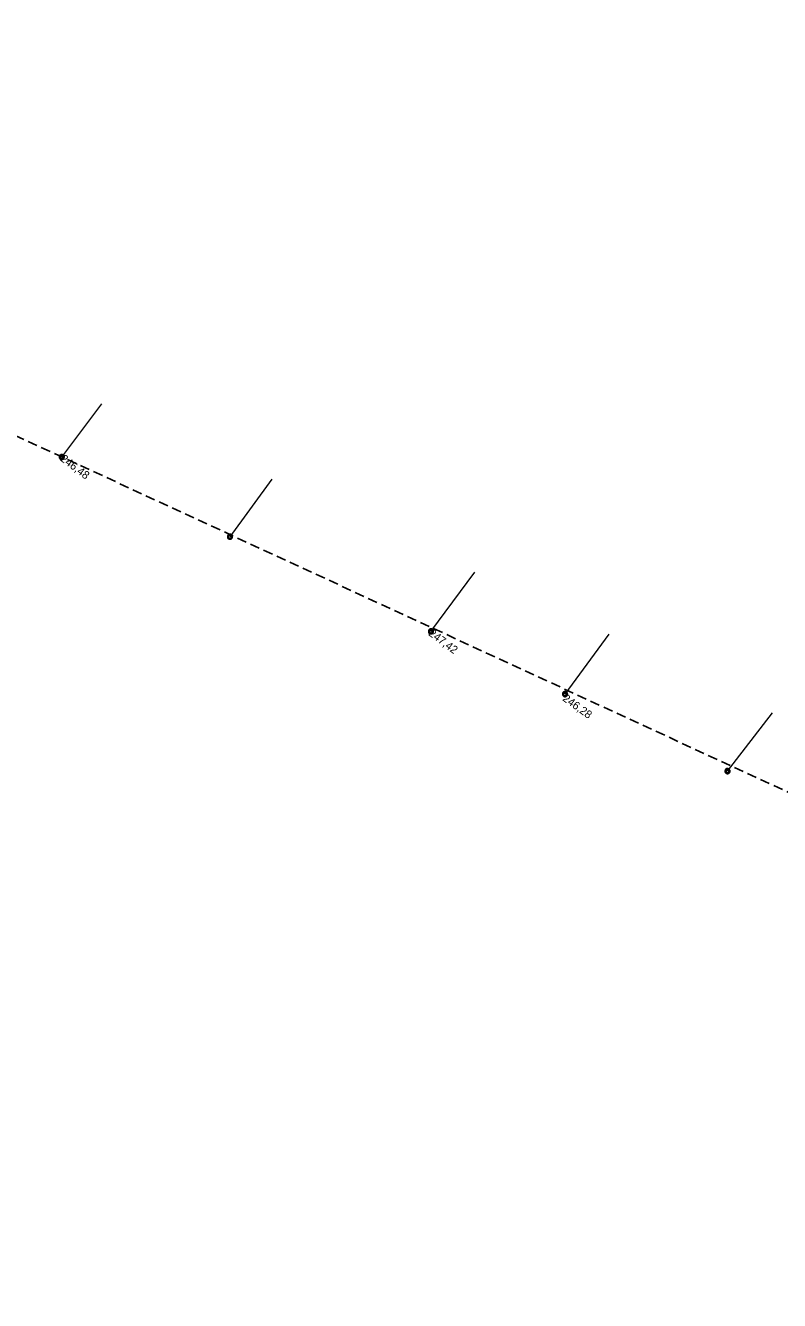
# Model space of a CAD drawing. Extents: x -735085 to -733500, y -1044153 to -1043402.
# Drawn here: x -734591.8 to -734516.4, y -1043690.4 to -1043562.9 of the extents above; entities that cross this region are included whole.
import ezdxf

# ---------------------------------------------------------------- set-up
doc = ezdxf.new("R2010")
doc.units = 0
doc.header["$LTSCALE"] = 0.32
doc.linetypes.add('MEDIUM_DASHED', pattern=[4.5, 3, -1.5])
doc.layers.add('16', color=7, linetype='Continuous')
for name, color, linetype, lineweight in [('18', 7, 'Continuous', 13), ('49', 7, 'Continuous', 13), ('63', 7, 'MEDIUM_DASHED', 25)]:
    doc.layers.add(name, color=color, linetype=linetype, lineweight=lineweight)

msp = doc.modelspace()

# ---------------------------------------------------------------- linework, layer by layer
at = {"layer": '18'}
for points in [[(-734587.874, -1043606.063), (-734587.88, -1043606.007), (-734587.897, -1043605.954), (-734587.926, -1043605.905), (-734587.964, -1043605.864), (-734588.01, -1043605.832), (-734588.062, -1043605.81), (-734588.117, -1043605.799), (-734588.173, -1043605.801), (-734588.228, -1043605.814), (-734588.279, -1043605.839), (-734588.323, -1043605.874), (-734588.359, -1043605.917), (-734588.384, -1043605.967), (-734588.399, -1043606.022), (-734588.402, -1043606.078), (-734588.393, -1043606.133), (-734588.372, -1043606.186), (-734588.341, -1043606.232), (-734588.301, -1043606.271), (-734588.253, -1043606.301), (-734588.2, -1043606.32), (-734588.144, -1043606.327), (-734588.088, -1043606.323), (-734588.034, -1043606.306), (-734587.985, -1043606.279), (-734587.943, -1043606.241), (-734587.91, -1043606.196), (-734587.887, -1043606.145), (-734587.875, -1043606.09)], [(-734587.933, -1043606.066), (-734587.939, -1043606.017), (-734587.957, -1043605.971), (-734587.985, -1043605.93), (-734588.022, -1043605.897), (-734588.066, -1043605.875), (-734588.114, -1043605.863), (-734588.163, -1043605.863), (-734588.211, -1043605.875), (-734588.255, -1043605.898), (-734588.292, -1043605.931), (-734588.32, -1043605.972), (-734588.337, -1043606.019), (-734588.343, -1043606.068), (-734588.336, -1043606.117), (-734588.318, -1043606.163), (-734588.29, -1043606.203), (-734588.253, -1043606.236), (-734588.209, -1043606.258), (-734588.16, -1043606.27), (-734588.111, -1043606.269), (-734588.063, -1043606.257), (-734588.02, -1043606.233), (-734587.983, -1043606.2), (-734587.955, -1043606.159), (-734587.939, -1043606.112)], [(-734587.992, -1043606.07), (-734587.998, -1043606.028), (-734588.015, -1043605.99), (-734588.043, -1043605.959), (-734588.078, -1043605.936), (-734588.118, -1043605.925), (-734588.16, -1043605.925), (-734588.2, -1043605.937), (-734588.235, -1043605.96), (-734588.262, -1043605.992), (-734588.279, -1043606.03), (-734588.284, -1043606.071), (-734588.278, -1043606.113), (-734588.26, -1043606.15), (-734588.232, -1043606.182), (-734588.196, -1043606.204), (-734588.156, -1043606.215), (-734588.114, -1043606.214), (-734588.074, -1043606.201), (-734588.04, -1043606.178), (-734588.013, -1043606.145), (-734587.997, -1043606.107)], [(-734571.056, -1043614.021), (-734571.061, -1043613.965), (-734571.078, -1043613.912), (-734571.107, -1043613.863), (-734571.146, -1043613.822), (-734571.191, -1043613.79), (-734571.244, -1043613.768), (-734571.299, -1043613.757), (-734571.355, -1043613.759), (-734571.409, -1043613.772), (-734571.46, -1043613.797), (-734571.505, -1043613.832), (-734571.541, -1043613.875), (-734571.566, -1043613.925), (-734571.581, -1043613.98), (-734571.583, -1043614.036), (-734571.575, -1043614.091), (-734571.554, -1043614.144), (-734571.522, -1043614.19), (-734571.482, -1043614.229), (-734571.434, -1043614.259), (-734571.382, -1043614.278), (-734571.326, -1043614.285), (-734571.269, -1043614.281), (-734571.215, -1043614.264), (-734571.166, -1043614.237), (-734571.125, -1043614.199), (-734571.092, -1043614.154), (-734571.068, -1043614.103), (-734571.056, -1043614.048)], [(-734571.115, -1043614.024), (-734571.12, -1043613.975), (-734571.139, -1043613.929), (-734571.166, -1043613.888), (-734571.203, -1043613.855), (-734571.247, -1043613.833), (-734571.296, -1043613.821), (-734571.345, -1043613.821), (-734571.392, -1043613.833), (-734571.436, -1043613.856), (-734571.473, -1043613.889), (-734571.502, -1043613.93), (-734571.519, -1043613.977), (-734571.524, -1043614.026), (-734571.517, -1043614.075), (-734571.5, -1043614.121), (-734571.472, -1043614.161), (-734571.434, -1043614.194), (-734571.391, -1043614.216), (-734571.342, -1043614.228), (-734571.293, -1043614.227), (-734571.245, -1043614.215), (-734571.201, -1043614.191), (-734571.164, -1043614.158), (-734571.137, -1043614.117), (-734571.12, -1043614.07)], [(-734571.174, -1043614.028), (-734571.179, -1043613.986), (-734571.196, -1043613.948), (-734571.225, -1043613.917), (-734571.259, -1043613.894), (-734571.299, -1043613.883), (-734571.342, -1043613.883), (-734571.382, -1043613.895), (-734571.416, -1043613.918), (-734571.443, -1043613.95), (-734571.46, -1043613.988), (-734571.465, -1043614.029), (-734571.46, -1043614.071), (-734571.441, -1043614.108), (-734571.414, -1043614.14), (-734571.377, -1043614.162), (-734571.338, -1043614.173), (-734571.296, -1043614.172), (-734571.255, -1043614.159), (-734571.222, -1043614.136), (-734571.195, -1043614.103), (-734571.179, -1043614.065)], [(-734550.964, -1043623.479), (-734550.97, -1043623.423), (-734550.987, -1043623.37), (-734551.016, -1043623.321), (-734551.054, -1043623.28), (-734551.1, -1043623.248), (-734551.152, -1043623.226), (-734551.207, -1043623.215), (-734551.263, -1043623.217), (-734551.318, -1043623.23), (-734551.369, -1043623.255), (-734551.413, -1043623.29), (-734551.449, -1043623.333), (-734551.474, -1043623.383), (-734551.489, -1043623.438), (-734551.492, -1043623.494), (-734551.483, -1043623.549), (-734551.462, -1043623.602), (-734551.431, -1043623.648), (-734551.391, -1043623.687), (-734551.343, -1043623.717), (-734551.29, -1043623.736), (-734551.234, -1043623.743), (-734551.178, -1043623.739), (-734551.124, -1043623.722), (-734551.075, -1043623.695), (-734551.033, -1043623.657), (-734551, -1043623.612), (-734550.977, -1043623.561), (-734550.965, -1043623.506)], [(-734551.023, -1043623.482), (-734551.029, -1043623.433), (-734551.047, -1043623.387), (-734551.075, -1043623.346), (-734551.112, -1043623.313), (-734551.156, -1043623.291), (-734551.204, -1043623.279), (-734551.253, -1043623.279), (-734551.301, -1043623.291), (-734551.345, -1043623.314), (-734551.382, -1043623.347), (-734551.41, -1043623.388), (-734551.427, -1043623.435), (-734551.433, -1043623.484), (-734551.426, -1043623.533), (-734551.408, -1043623.579), (-734551.38, -1043623.619), (-734551.343, -1043623.652), (-734551.299, -1043623.674), (-734551.25, -1043623.686), (-734551.201, -1043623.685), (-734551.153, -1043623.673), (-734551.11, -1043623.649), (-734551.073, -1043623.616), (-734551.045, -1043623.575), (-734551.029, -1043623.528)], [(-734551.082, -1043623.486), (-734551.088, -1043623.444), (-734551.105, -1043623.406), (-734551.133, -1043623.375), (-734551.168, -1043623.352), (-734551.208, -1043623.341), (-734551.25, -1043623.341), (-734551.29, -1043623.353), (-734551.325, -1043623.376), (-734551.352, -1043623.408), (-734551.369, -1043623.446), (-734551.374, -1043623.487), (-734551.368, -1043623.529), (-734551.35, -1043623.566), (-734551.322, -1043623.598), (-734551.286, -1043623.62), (-734551.246, -1043623.631), (-734551.204, -1043623.63), (-734551.164, -1043623.617), (-734551.13, -1043623.594), (-734551.103, -1043623.561), (-734551.087, -1043623.523)], [(-734537.562, -1043629.756), (-734537.568, -1043629.7), (-734537.585, -1043629.647), (-734537.614, -1043629.598), (-734537.652, -1043629.557), (-734537.698, -1043629.525), (-734537.75, -1043629.503), (-734537.805, -1043629.492), (-734537.861, -1043629.494), (-734537.916, -1043629.507), (-734537.967, -1043629.532), (-734538.011, -1043629.567), (-734538.047, -1043629.61), (-734538.072, -1043629.66), (-734538.087, -1043629.715), (-734538.09, -1043629.771), (-734538.081, -1043629.826), (-734538.06, -1043629.879), (-734538.029, -1043629.925), (-734537.989, -1043629.964), (-734537.941, -1043629.994), (-734537.888, -1043630.013), (-734537.832, -1043630.02), (-734537.776, -1043630.016), (-734537.722, -1043629.999), (-734537.673, -1043629.972), (-734537.631, -1043629.934), (-734537.598, -1043629.889), (-734537.575, -1043629.838), (-734537.563, -1043629.783)], [(-734537.621, -1043629.759), (-734537.627, -1043629.71), (-734537.645, -1043629.664), (-734537.673, -1043629.623), (-734537.71, -1043629.59), (-734537.754, -1043629.568), (-734537.802, -1043629.556), (-734537.851, -1043629.556), (-734537.899, -1043629.568), (-734537.943, -1043629.591), (-734537.98, -1043629.624), (-734538.008, -1043629.665), (-734538.025, -1043629.712), (-734538.031, -1043629.761), (-734538.024, -1043629.81), (-734538.006, -1043629.856), (-734537.978, -1043629.896), (-734537.941, -1043629.929), (-734537.897, -1043629.951), (-734537.848, -1043629.963), (-734537.799, -1043629.962), (-734537.751, -1043629.95), (-734537.708, -1043629.926), (-734537.671, -1043629.893), (-734537.643, -1043629.852), (-734537.627, -1043629.805)], [(-734537.68, -1043629.763), (-734537.686, -1043629.721), (-734537.703, -1043629.683), (-734537.731, -1043629.652), (-734537.766, -1043629.629), (-734537.806, -1043629.618), (-734537.848, -1043629.618), (-734537.888, -1043629.63), (-734537.923, -1043629.653), (-734537.95, -1043629.685), (-734537.967, -1043629.723), (-734537.972, -1043629.764), (-734537.966, -1043629.806), (-734537.948, -1043629.843), (-734537.92, -1043629.875), (-734537.884, -1043629.897), (-734537.844, -1043629.908), (-734537.802, -1043629.907), (-734537.762, -1043629.894), (-734537.728, -1043629.871), (-734537.701, -1043629.838), (-734537.685, -1043629.8)], [(-734521.321, -1043637.453), (-734521.326, -1043637.397), (-734521.343, -1043637.344), (-734521.372, -1043637.295), (-734521.411, -1043637.254), (-734521.456, -1043637.222), (-734521.509, -1043637.2), (-734521.564, -1043637.189), (-734521.62, -1043637.191), (-734521.674, -1043637.204), (-734521.725, -1043637.229), (-734521.77, -1043637.264), (-734521.806, -1043637.307), (-734521.831, -1043637.357), (-734521.846, -1043637.412), (-734521.848, -1043637.468), (-734521.84, -1043637.523), (-734521.819, -1043637.576), (-734521.788, -1043637.622), (-734521.747, -1043637.661), (-734521.7, -1043637.691), (-734521.647, -1043637.71), (-734521.591, -1043637.717), (-734521.534, -1043637.713), (-734521.48, -1043637.696), (-734521.431, -1043637.669), (-734521.39, -1043637.631), (-734521.357, -1043637.586), (-734521.333, -1043637.535), (-734521.321, -1043637.48)], [(-734521.38, -1043637.456), (-734521.386, -1043637.407), (-734521.404, -1043637.361), (-734521.431, -1043637.32), (-734521.468, -1043637.287), (-734521.512, -1043637.265), (-734521.561, -1043637.253), (-734521.61, -1043637.253), (-734521.657, -1043637.265), (-734521.701, -1043637.288), (-734521.739, -1043637.321), (-734521.767, -1043637.362), (-734521.784, -1043637.409), (-734521.789, -1043637.458), (-734521.782, -1043637.507), (-734521.765, -1043637.553), (-734521.737, -1043637.593), (-734521.7, -1043637.626), (-734521.656, -1043637.648), (-734521.607, -1043637.66), (-734521.558, -1043637.659), (-734521.51, -1043637.647), (-734521.467, -1043637.623), (-734521.429, -1043637.59), (-734521.402, -1043637.549), (-734521.386, -1043637.502)], [(-734521.439, -1043637.46), (-734521.445, -1043637.418), (-734521.462, -1043637.38), (-734521.49, -1043637.349), (-734521.524, -1043637.326), (-734521.565, -1043637.315), (-734521.607, -1043637.315), (-734521.647, -1043637.327), (-734521.681, -1043637.35), (-734521.708, -1043637.382), (-734521.725, -1043637.42), (-734521.73, -1043637.461), (-734521.725, -1043637.503), (-734521.706, -1043637.54), (-734521.679, -1043637.572), (-734521.642, -1043637.594), (-734521.603, -1043637.605), (-734521.561, -1043637.604), (-734521.521, -1043637.591), (-734521.487, -1043637.568), (-734521.46, -1043637.535), (-734521.444, -1043637.497)]]:
    msp.add_lwpolyline(points, close=True, dxfattribs=at)
at = {"layer": '49'}
for p, q in [((-734588.138, -1043606.076), (-734584.146, -1043600.733)), ((-734588.138, -1043606.076), (-734584.146, -1043600.733)), ((-734571.32, -1043614.034), (-734567.114, -1043608.256)), ((-734571.32, -1043614.034), (-734567.114, -1043608.256)), ((-734551.228, -1043623.492), (-734546.857, -1043617.578)), ((-734551.228, -1043623.492), (-734546.857, -1043617.578)), ((-734537.826, -1043629.769), (-734533.412, -1043623.765)), ((-734537.826, -1043629.769), (-734533.412, -1043623.765)), ((-734521.585, -1043637.466), (-734517.096, -1043631.641)), ((-734521.585, -1043637.466), (-734517.096, -1043631.641))]:
    msp.add_line(p, q, dxfattribs=at)
at = {"layer": '63'}
msp.add_lwpolyline([(-734957.565, -1043435.501), (-734250.468, -1043761.931)], dxfattribs=at)

# ---------------------------------------------------------------- texts
at = {"layer": '16'}
for s, rotation, p in [('246,48', 323, (-734588.356, -1043606.369)), ('247,42', 323, (-734551.541, -1043623.817)), ('246,28', 324, (-734538.14, -1043630.342))]:
    msp.add_text(s, height=0.8, rotation=rotation, dxfattribs=at).set_placement(p)

doc.saveas('drawing.dxf')
